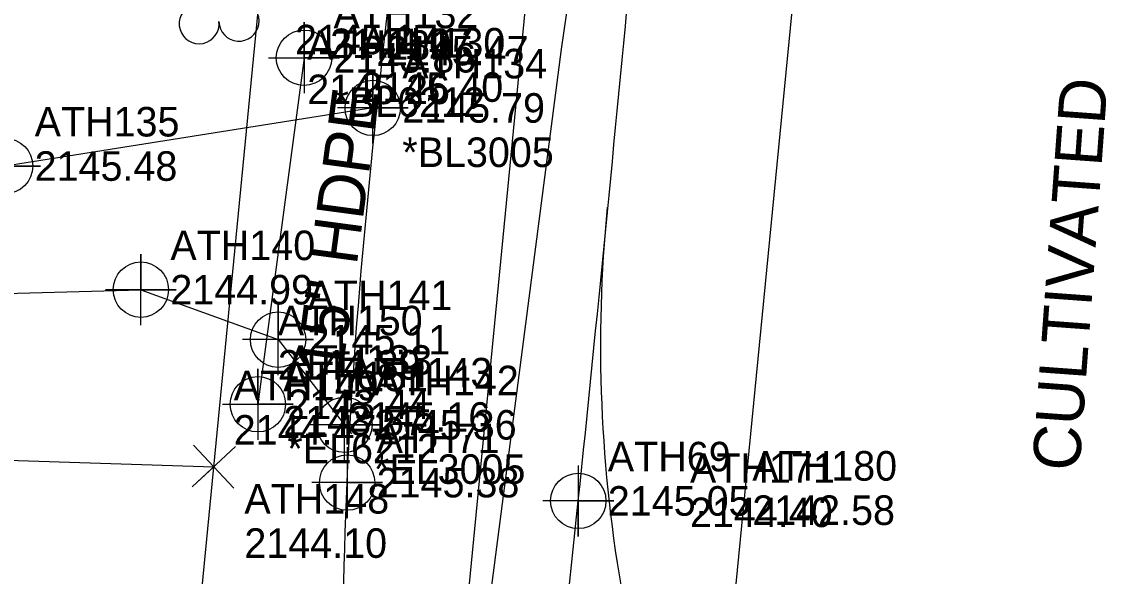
# Model space of a CAD drawing. Extents: x 890923 to 892150, y 696020 to 698102.
# Drawn here: x 891400.8 to 891493.6, y 696848.9 to 696895.8 of the extents above; entities that cross this region are included whole.
import ezdxf

# ---------------------------------------------------------------- set-up
doc = ezdxf.new("R2010")
doc.units = 0
for name, color, linetype in [('Exist DTM Breakline Cogo Elevation', 7, 'Continuous'), ('Exist DTM Breakline Cogo Number', 7, 'Continuous'), ('Exist Horizontal Alignment', 7, 'Continuous'), ('Exist Property Corner CELL', 7, 'Continuous'), ('Exist Property Line', 7, 'Continuous'), ('Exist Right of Way Line', 7, 'Continuous'), ('Exist Roads EOP', 7, 'Continuous'), ('Exist Roads EOP Cogo Elevation', 7, 'Continuous'), ('Exist Roads EOP Cogo Number', 7, 'Continuous'), ('Exist Roads EOP Cogo Point CELL', 7, 'Continuous'), ('Exist Roads Soil', 7, 'Continuous'), ('Exist Roads Soil Cogo Comment', 7, 'Continuous'), ('Exist Roads Soil Cogo Elevation', 7, 'Continuous'), ('Exist Roads Soil Cogo Number', 7, 'Continuous'), ('Exist Roads Soil Cogo Point CELL', 7, 'Continuous'), ('Exist Structure Minor Pipes HDPE 12 Inch Cogo Comment', 7, 'Continuous'), ('Exist Structure Minor Pipes HDPE 12 Inch Cogo Elevation', 7, 'Continuous'), ('Exist Structure Minor Pipes HDPE 12 Inch Cogo Number', 7, 'Continuous'), ('Exist Structure Minor Pipes HDPE 12 Inch Cogo Point CELL', 7, 'Continuous'), ('Exist Structure Minor Pipes HDPE 15 Inch', 7, 'Continuous'), ('Exist Structure Minor Pipes HDPE 15 Inch Text', 7, 'Continuous'), ('Exist Utilities Telephone UG Cable SUE LOS C', 7, 'Continuous'), ('Exist Vegetation Tree CELL', 7, 'Continuous'), ('Exist Vegetation Tree Text', 7, 'Continuous')]:
    doc.layers.add(name, color=color, linetype=linetype)

msp = doc.modelspace()

# ---------------------------------------------------------------- linework, layer by layer
at = {"layer": 'Exist Horizontal Alignment'}
msp.add_line((891438.213, 696843.584), (891452.084, 696985.946), dxfattribs=at)
at = {"layer": 'Exist Property Corner CELL'}
msp.add_line((891417.026, 696858.157), (891417.026, 696858.157), dxfattribs=at)
msp.add_lwpolyline([(891418.85, 696859.867), (891415.202, 696856.447), (891417.026, 696858.157), (891418.736, 696856.333), (891415.316, 696859.981)], dxfattribs=at)
at = {"layer": 'Exist Property Line'}
msp.add_line((891337.695, 696860.719), (891417.026, 696858.157), dxfattribs=at)
at = {"layer": 'Exist Right of Way Line'}
for p, q in [((891415.819, 696845.766), (891429.69, 696988.128)), ((891460.607, 696841.402), (891474.478, 696983.764))]:
    msp.add_line(p, q, dxfattribs=at)
msp.add_arc((891570.512, 696868.42), 120.739, 174.43491, 206.04523, dxfattribs=at)
at = {"layer": 'Exist Roads EOP'}
for points in [[(891436.065, 696777.901), (891429.791, 696812.087), (891428.317, 696856.808), (891432.62, 696904.522)], [(891450.361, 696786.935), (891446.047, 696811.796), (891447.892, 696855.26), (891452.429, 696901.16)]]:
    msp.add_spline(points, degree=3, dxfattribs=at)
at = {"layer": 'Exist Roads EOP Cogo Point CELL'}
for points in [[(891428.317, 696859.808), (891428.317, 696853.808), (891428.317, 696856.808), (891431.317, 696856.808), (891425.317, 696856.808)], [(891447.892, 696858.26), (891447.892, 696852.26), (891447.892, 696855.26), (891450.892, 696855.26), (891444.892, 696855.26)]]:
    msp.add_lwpolyline(points, dxfattribs=at)
for centre in [(891428.317, 696856.808), (891447.892, 696855.26)]:
    msp.add_circle(centre, 2.344, dxfattribs=at)
at = {"layer": 'Exist Roads Soil'}
for points in [[(891431.186, 696888.626), (891399.354, 696883.599), (891370.728, 696880.657), (891358.372, 696880.028)], [(891357.898, 696871.265), (891380.515, 696872.313), (891410.847, 696873.136), (891422.467, 696868.908), (891428.688, 696860.934)]]:
    msp.add_lwpolyline(points, dxfattribs=at)
at = {"layer": 'Exist Roads Soil Cogo Point CELL'}
for points in [[(891430.489, 696885.516), (891430.489, 696891.516), (891430.489, 696888.516), (891433.489, 696888.516), (891427.489, 696888.516)], [(891399.354, 696880.599), (891399.354, 696886.599), (891399.354, 696883.599), (891402.354, 696883.599), (891396.354, 696883.599)], [(891410.847, 696870.136), (891410.847, 696876.136), (891410.847, 696873.136), (891413.847, 696873.136), (891407.847, 696873.136)], [(891422.467, 696865.908), (891422.467, 696871.908), (891422.467, 696868.908), (891425.467, 696868.908), (891419.467, 696868.908)], [(891428.09, 696858.7), (891428.09, 696864.7), (891428.09, 696861.7), (891431.09, 696861.7), (891425.09, 696861.7)]]:
    msp.add_lwpolyline(points, dxfattribs=at)
for centre in [(891430.489, 696888.516), (891399.354, 696883.599), (891410.847, 696873.136), (891422.467, 696868.908), (891428.09, 696861.7)]:
    msp.add_circle(centre, 2.344, dxfattribs=at)
at = {"layer": 'Exist Structure Minor Pipes HDPE 12 Inch Cogo Point CELL'}
for points in [[(891421.665, 696892.76), (891427.665, 696892.76), (891424.665, 696892.76), (891424.665, 696895.76), (891424.665, 696889.76)], [(891417.758, 696863.437), (891423.758, 696863.437), (891420.758, 696863.437), (891420.758, 696866.437), (891420.758, 696860.437)]]:
    msp.add_lwpolyline(points, dxfattribs=at)
for centre in [(891424.665, 696892.76), (891420.758, 696863.437)]:
    msp.add_circle(centre, 2.344, dxfattribs=at)
at = {"layer": 'Exist Structure Minor Pipes HDPE 15 Inch'}
msp.add_line((891424.665, 696892.76), (891420.758, 696863.437), dxfattribs=at)
at = {"layer": 'Exist Utilities Telephone UG Cable SUE LOS C'}
msp.add_lwpolyline([(891624.207, 696480.847), (891618.841, 696483.249), (891605.515, 696493.812), (891596.776, 696509.474), (891581.554, 696537.801), (891557.633, 696577.04), (891541.1, 696603.159), (891515.219, 696655.328), (891488.396, 696708.509), (891478.287, 696732.52), (891479.355, 696741.044), (891472.86, 696758.331), (891457.587, 696793.76), (891442.378, 696819.058), (891440.139, 696844.841), (891446.482, 696893.479), (891454.409, 696947.998), (891458.347, 696977.764), (891460.653, 697014.116), (891458.015, 697062.172), (891453.445, 697070.877), (891449.028, 697077.737), (891443.563, 697082.562), (891429.064, 697082.113)], dxfattribs=at)
at = {"layer": 'Exist Vegetation Tree CELL'}
for centre, radius, start, end in [((891419.162, 696895.86), 1.698, 181.28216, 74.55999), ((891415.785, 696895.638), 1.689, 111.56708, 6.23104)]:
    msp.add_arc(centre, radius, start, end, dxfattribs=at)

# ---------------------------------------------------------------- texts
at = {"layer": 'Exist DTM Breakline Cogo Elevation'}
for s, p in [('2145.17', (891423.906, 696893.05)), ('2144.07', (891426.879, 696892.733)), ('2145.47', (891431.597, 696892.112)), ('2145.26', (891424.94, 696888.838)), ('2145.40', (891429.447, 696889.031)), ('2144.89', (891422.449, 696865.523)), ('2143.57', (891422.908, 696860.797)), ('2145.16', (891428.354, 696861.112)), ('2144.47', (891418.713, 696860.026)), ('2144.40', (891457.35, 696853.044)), ('2142.58', (891462.626, 696853.227)), ('2144.10', (891419.616, 696850.44))]:
    msp.add_text(s, height=2.5, dxfattribs=at).set_placement(p)
at = {"layer": 'Exist DTM Breakline Cogo Number'}
for s, p in [('ATH131', (891424.94, 696892.588)), ('ATH130', (891429.447, 696892.781)), ('ATH150', (891422.449, 696869.273)), ('ATH151', (891422.908, 696864.547)), ('ATH143', (891428.354, 696864.862)), ('ATH149', (891418.713, 696863.776)), ('ATH171', (891457.35, 696856.794)), ('ATH180', (891462.626, 696856.977)), ('ATH148', (891419.616, 696854.19))]:
    msp.add_text(s, height=2.5, dxfattribs=at).set_placement(p)
at = {"layer": 'Exist Roads EOP Cogo Elevation'}
for s, p in [('2145.38', (891430.817, 696855.558)), ('2145.05', (891450.392, 696854.01))]:
    msp.add_text(s, height=2.5, dxfattribs=at).set_placement(p)
at = {"layer": 'Exist Roads EOP Cogo Number'}
for s, p in [('ATH71', (891430.817, 696859.308)), ('ATH69', (891450.392, 696857.76))]:
    msp.add_text(s, height=2.5, dxfattribs=at).set_placement(p)
at = {"layer": 'Exist Roads Soil Cogo Comment'}
for s, p in [('*BL3005', (891432.989, 696883.516)), ('*EL3005', (891430.59, 696856.7))]:
    msp.add_text(s, height=2.5, dxfattribs=at).set_placement(p)
at = {"layer": 'Exist Roads Soil Cogo Elevation'}
for s, p in [('2145.79', (891432.989, 696887.266)), ('2145.48', (891401.854, 696882.349)), ('2144.99', (891413.347, 696871.886)), ('2145.11', (891424.967, 696867.658)), ('2145.36', (891430.59, 696860.45))]:
    msp.add_text(s, height=2.5, dxfattribs=at).set_placement(p)
at = {"layer": 'Exist Roads Soil Cogo Number'}
for s, p in [('ATH134', (891432.989, 696891.016)), ('ATH135', (891401.854, 696886.099)), ('ATH140', (891413.347, 696875.636)), ('ATH141', (891424.967, 696871.408)), ('ATH142', (891430.59, 696864.2))]:
    msp.add_text(s, height=2.5, dxfattribs=at).set_placement(p)
at = {"layer": 'Exist Structure Minor Pipes HDPE 12 Inch Cogo Comment'}
for s, p in [('*BL6212', (891427.165, 696887.76)), ('*EL6212', (891423.258, 696858.437))]:
    msp.add_text(s, height=2.5, dxfattribs=at).set_placement(p)
at = {"layer": 'Exist Structure Minor Pipes HDPE 12 Inch Cogo Elevation'}
for s, p in [('2143.86', (891427.165, 696891.51)), ('2143.44', (891423.258, 696862.187))]:
    msp.add_text(s, height=2.5, dxfattribs=at).set_placement(p)
at = {"layer": 'Exist Structure Minor Pipes HDPE 12 Inch Cogo Number'}
for s, p in [('ATH132', (891427.165, 696895.26)), ('ATH133', (891423.258, 696865.937))]:
    msp.add_text(s, height=2.5, dxfattribs=at).set_placement(p)
at = {"layer": 'Exist Structure Minor Pipes HDPE 15 Inch Text'}
msp.add_text('15" HDPE', height=4, rotation=82.4106, dxfattribs=at).set_placement((891427.892, 696865.873))
at = {"layer": 'Exist Vegetation Tree Text'}
msp.add_text('CULTIVATED', height=4, rotation=85.84446, dxfattribs=at).set_placement((891490.322, 696857.707))

doc.saveas('drawing.dxf')
